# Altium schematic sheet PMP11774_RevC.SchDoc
size 431 x 279 mm; Date: Not shown in title block; ApprovedBy: Not shown in title block; CheckedBy: Not shown in title block; Author: Not shown in title block; CompanyName: Not shown in title block; Engineer: Not shown in title block; Organization: Not shown in title block; Address1: Not shown in title block; Address2: Not shown in title block; Address3: Not shown in title block; Address4: Not shown in title block; DocumentNumber: 1; Revision: Use project parameter SCH_Rev; SheetNumber: 1; SheetTotal: 2; PageSetup: Record=PageOptions¦CenterHorizontal=True¦CenterVertical=True¦PrintScale=0.66¦XCorrection=1.00¦YCorrection=1.00¦PrintKind=0¦BorderSize=5000000¦LeftOffset=0¦BottomOffset=0¦Orientation=2¦PaperLength=4200¦PaperWidth=2970¦Scale=100¦PaperSource=7¦PrintQuality=-3¦MediaType=1¦DitherType=10¦PrintScaleMode=1¦PaperKind=A4¦PaperIndex=9
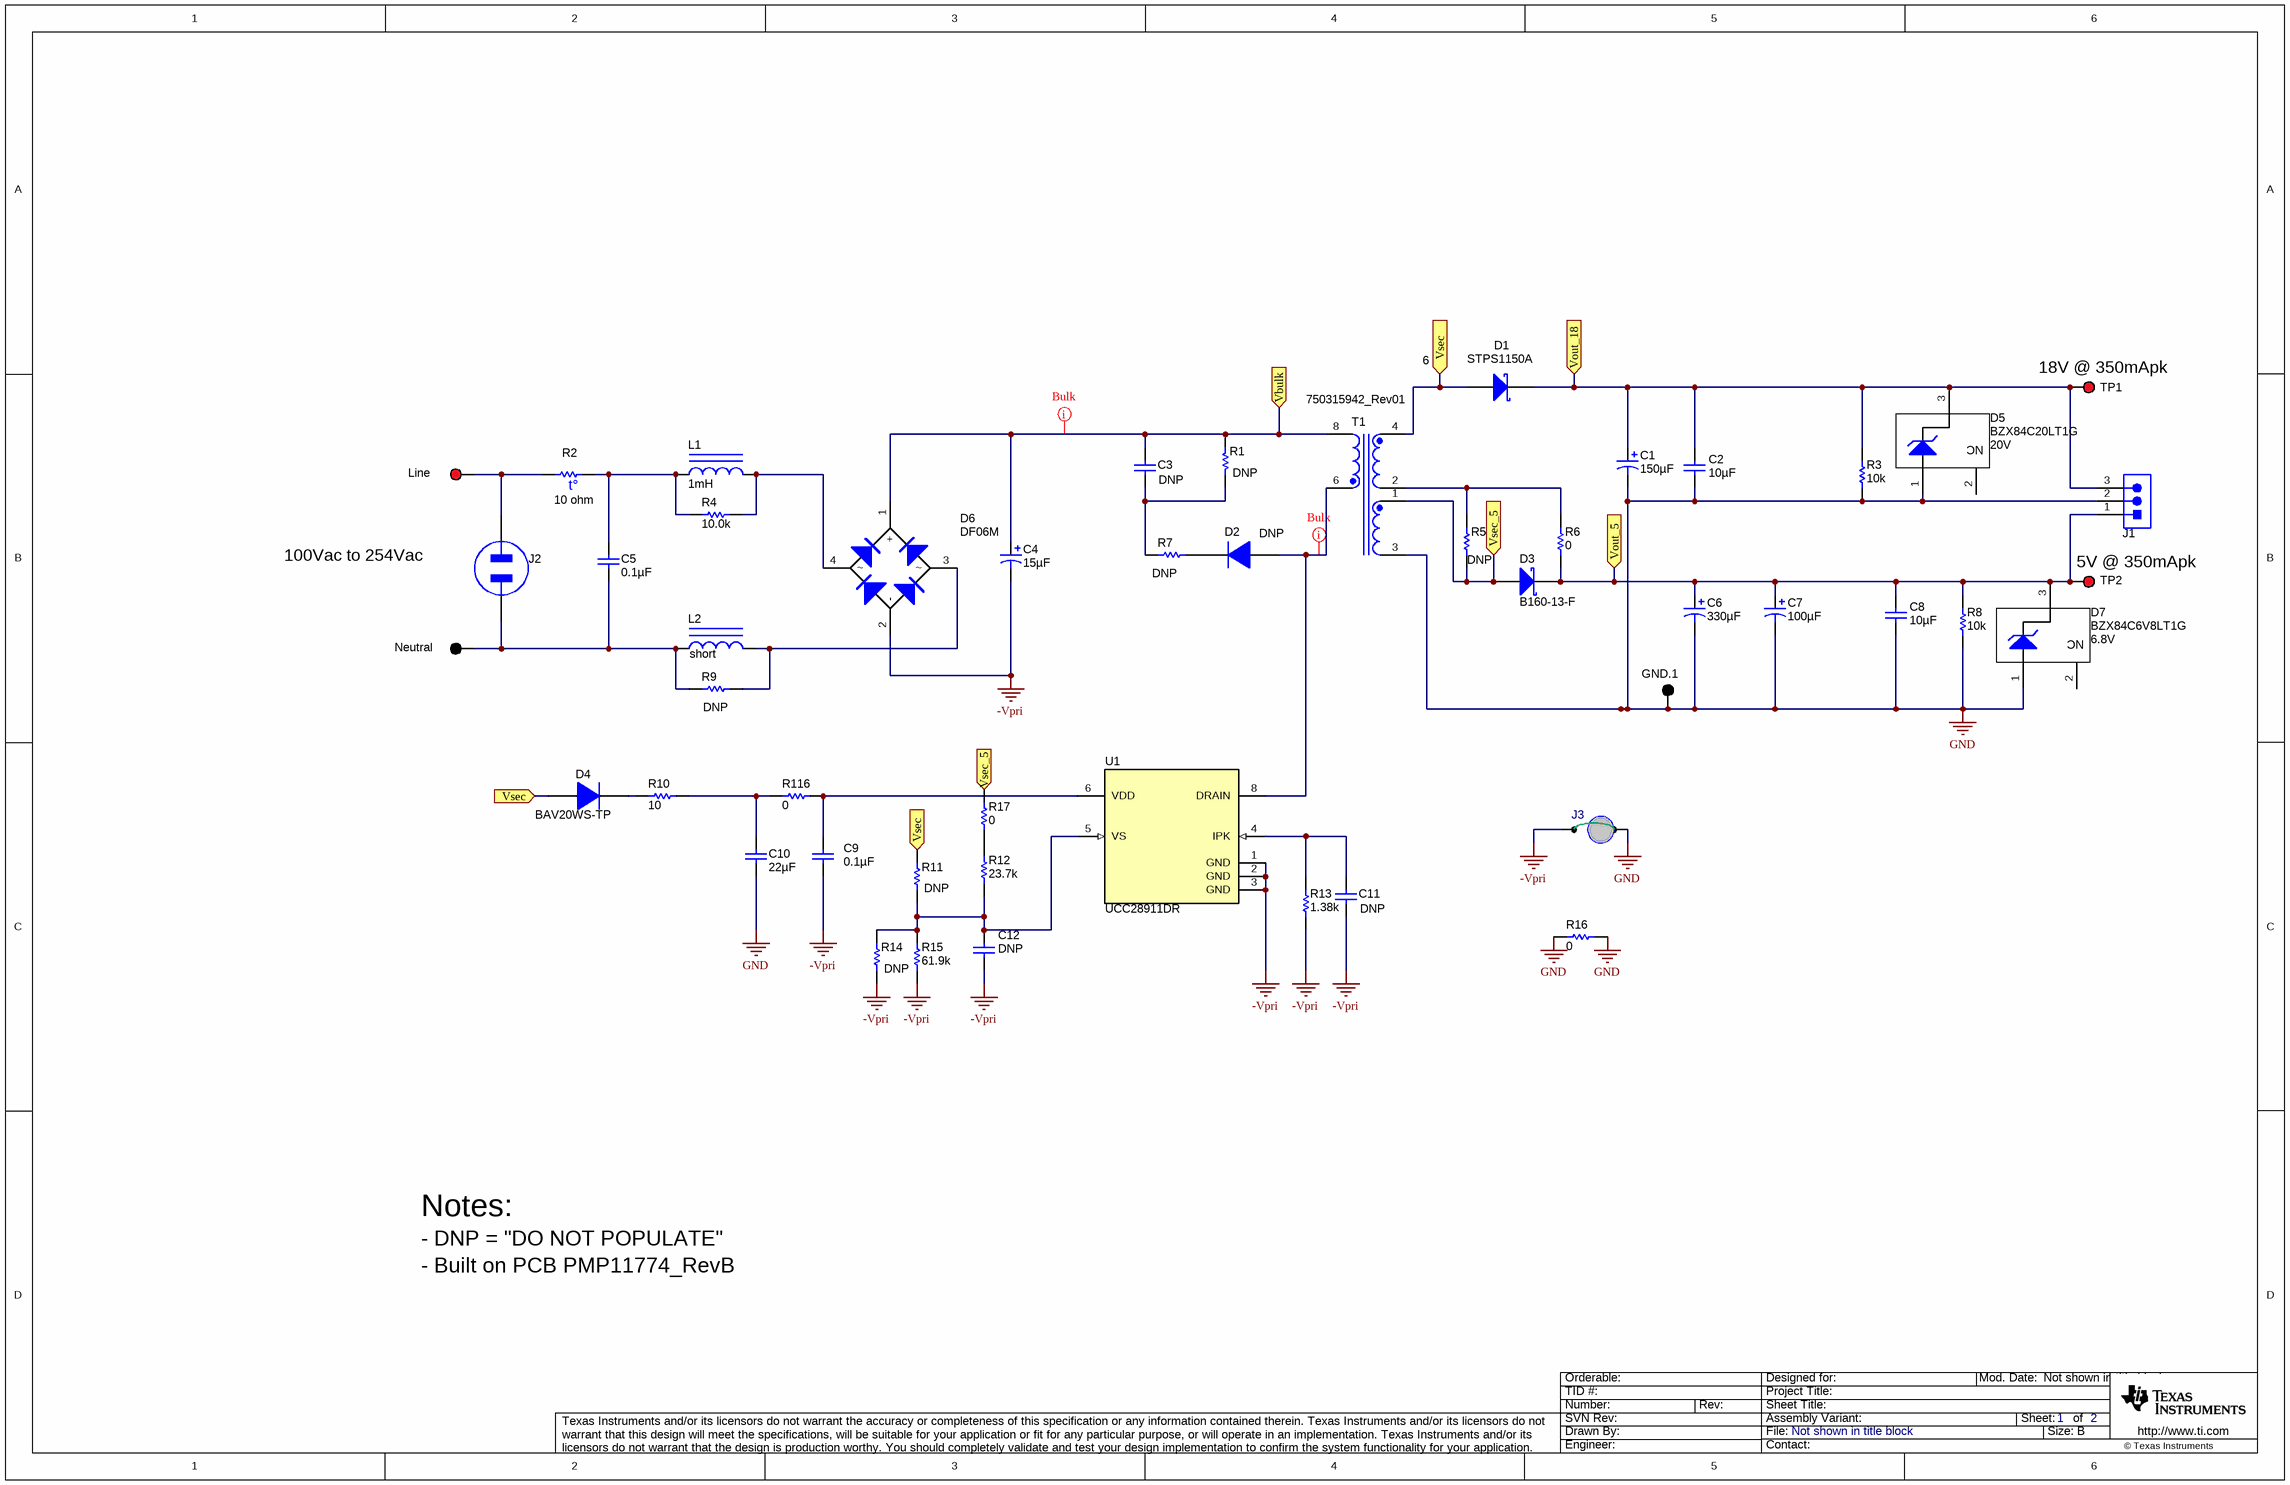
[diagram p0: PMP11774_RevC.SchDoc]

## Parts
C1  ValueDisplayed: 150µF  [FR_630x1120]  (hidden comment: EEU-FR1E151B)
C2  ValueDisplayed: 10µF  [1210]  (hidden comment: GRM32ER71H106KA12L)
C3  value DNP  [0805_HV1]  (hidden comment: QMK212B7102KD-T)
C4  ValueDisplayed: 15µF  [CAPPR5-12.5X20]  (hidden comment: EEUED2G150)
C5  ValueDisplayed: 0.1µF  [R46_1300x1200x600]  (hidden comment: R46KF310050P0K)
C6  ValueDisplayed: 330µF  [ZLH_630x1100]  (hidden comment: 10ZLH330MEFC6.3X11)
C7  ValueDisplayed: 100µF  [FM_630x1120]  (hidden comment: EEU-FM1E101)
C8  ValueDisplayed: 10µF  [1210]  (hidden comment: GRM32ER71H106KA12L)
C9  ValueDisplayed: 0.1µF  [0603]  (hidden comment: 06035C104KAT2A)
C10  ValueDisplayed: 22µF  [1210]  (hidden comment: GRM32ER61E226KE15L)
C11  value DNP  [0603]  (hidden comment: 06035A100JAT2A)
C12  value DNP  [0603]  (hidden comment: 06035A100JAT2A)
D1  STPS1150A  [SMA]
D2  value DNP  [powerDI123]  (hidden comment: DFLR1600-7)
D3  B160-13-F  [SMA]
D4  BAV20WS-TP  [sod-323]
D5  BZX84C20LT1G  value 20V  [SOT-23]
D6  DF06M  [DIOB_DFM]
D7  BZX84C6V8LT1G  value 6.8V  [SOT-23]
GND.1  5001  [Keystone5001]  (value not drawn)
J1  1757255  [TE_1757255]  (value not drawn)
J2  770W-X2/10  [CONN_AC_770W-SERIES]  (value not drawn)
J3  923345-05-C  [923345-05-C]  (value not drawn)
L1  ValueDisplayed: 1mH  [WE-TI_8012]  (hidden comment: 744743102)
L2  value short  [WE-TI_8012]  (hidden comment: 744743102)
Line  5000  [Keystone5000]  (value not drawn)
Neutral  5001  [Keystone5001]  (value not drawn)
R1  value DNP  [1206]  (hidden comment: RC1206FR-07120KL)
R2  value 10 ohm  [THERM_B57236S0]  (hidden comment: B57236S0100M000)
R3  ValueDisplayed: 10k  [0805_HV]  (hidden comment: CRCW080510K0JNEA)
R4  ValueDisplayed: 10.0k  [1206]  (hidden comment: RC1206FR-0710KL)
R5  value DNP  [0805_HV]  (hidden comment: CRCW08050000Z0EA)
R6  ValueDisplayed: 0  [0805_HV]  (hidden comment: CRCW08050000Z0EA)
R7  value DNP  [1206]  (hidden comment: CRCW120610R0JNEA)
R8  ValueDisplayed: 10k  [0805_HV]  (hidden comment: CRCW080510K0JNEA)
R9  value DNP  [1206]  (hidden comment: RC1206FR-0710KL)
R10  ValueDisplayed: 10  [0603]  (hidden comment: CRCW060310R0JNEAHP)
R11  value DNP  [0603]  (hidden comment: CRCW0603110KFKEA)
R12  ValueDisplayed: 23.7k  [0603]  (hidden comment: CRCW060323K7FKEA)
R13  ValueDisplayed: 1.38k  [0603]  (hidden comment: RT0603BRD071K38L)
R14  value DNP  [0603]  (hidden comment: CRCW060391K0JNEA)
R15  ValueDisplayed: 61.9k  [0603]  (hidden comment: RC0603FR-0761K9L)
R16  ValueDisplayed: 0  [RES_TH_CF14]
R17  ValueDisplayed: 0  [1206]  (hidden comment: CRCW12060000Z0EA)
R116  ValueDisplayed: 0  [RES_TH_CF14]
T1  750315942_Rev01  [Wurth_070-5420]
TP1  5000  [Keystone5000]  (value not drawn)
TP2  5000  [Keystone5000]  (value not drawn)
U1  UCC28911DR  [D0007A_N]

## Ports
Vbulk, Vout_5, Vout_18, Vsec, Vsec (in), Vsec_5, Vsec_5 (in)

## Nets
-Vpri: C4.2(-) C9.2 C11.1 C12.1 D6.2(-) J3.1 R13.1 R14.1 R15.1 U1.1(GND) U1.2(GND) U1.3(GND)
GND: C1.2(-) C2.2 C6.2(-) C7.2(-) C8.2 C10.2 D5.1(A) D7.1(A) GND.1.1 J1.2 J3.2 R3.1 R8.1 R16.1 R16.2 T1.3
Vbulk: C3.2 C4.1(+) D6.1(+) R1.1 T1.8 ; port Vbulk
Vout_5: C6.1(+) C7.1(+) C8.1 D3.1(K) D7.3(K) J1.1 R6.1 R8.2 TP2.1 ; port Vout_5
Vout_18: C1.1(+) C2.1 D1.1(K) D5.3(K) J1.3 R3.2 TP1.1 ; port Vout_18
Vsec: D1.2(A) D4.2(A) R11.2 T1.4 ; port Vsec
Vsec_5: D3.2(A) R5.1 R17.2 T1.1 ; port Vsec_5
NetC3_1: C3.1 R1.2 R7.2
NetC5_1: C5.1 L1.1 R2.2 R4.1
NetC5_2: C5.2 J2.1(Neutral) L2.1 Neutral.1 R9.1
NetC9_1: C9.1 R116.2 U1.6(VDD)
NetC10_1: C10.1 R10.2 R116.1
NetC11_2: C11.2 R13.2 U1.4(IPK)
NetC12_2: C12.2 R11.1 R12.1 R14.2 R15.2 U1.5(VS)
NetD2_1: D2.1(K) R7.1
NetD2_2: D2.2(A) T1.6 U1.8(DRAIN)
NetD4_1: D4.1(K) R10.1
NetD6_3: D6.3 L2.2 R9.2
NetD6_4: D6.4 L1.2 R4.2
NetJ2_2: J2.2(Hot) Line.1 R2.1
NetR5_2: R5.2 R6.2 T1.2
NetR12_2: R12.2 R17.1

Not connected (* = marked no-connect by the designer): D5 2(NC); D7 2(NC)

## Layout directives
rule Clearance Constraint [Clearance = 33mil]: Vbulk
rule Clearance Constraint [Clearance = 34mil]: NetD2_2

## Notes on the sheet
- 6
- (near TP1) 18V @ 350mApk
- 100Vac to 254Vac
- (near TP2) 5V @ 350mApk
- Notes:
- - DNP = "DO NOT POPULATE"
- - Built on PCB PMP11774_RevB

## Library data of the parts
C1 = EEU-FR1E151B: CAP, AL, 150 µF, 25 V, +/- 20%,  ohm, TH; Manufacturer: Panasonic; Polarized: Y; CompType: Capacitor; Value: 150uF; U/M: EA; Cap_F: 0.00015; Tolerance_%: 20; Value1: Unknown; VDC_V: 25; Value2: 25V; IRMS_A: 0.455; TaMin_C: -40; TaMax_C: 105; Cap_Case: 6.3x11.2mm
C2 C8 = GRM32ER71H106KA12L: CAP, CERM, 10uF, 50V, +/-10%, X7R, 1210; Manufacturer: MuRata; Polarized: N; CompType: Capacitor; U/M: EA; Cap_F: 0.00001; Tolerance_%: 10; Value1: Unknown; VDC_V: 50; TaMin_C: -55; TaMax_C: 125
C3 = QMK212B7102KD-T: CAP, CERM, 1000 pF, 250 V, +/- 10%, X7R, 0805; Manufacturer: Taiyo Yuden; Polarized: N; CompType: Capacitor; ValueDisplayed: 1000pF; U/M: EA; Cap_F: 0.000000001; Tolerance_%: 10; Value1: Unknown; VDC_V: 250; Value2: 250V; TaMin_C: -55; TaMax_C: 125; Cap_Case: 0805; AEC Category: Q200
C4 = EEUED2G150: CAP, AL, 15 µF, 400 V, +/- 20%, 1.909859 ohm, TH; Manufacturer: Panasonic; Polarized: Y; CompType: Capacitor; Value: 15uF; U/M: EA; Cap_F: 0.000015; Tolerance_%: 20; VDC_V: 400; Value2: 400V; IRMS_A: 0.41; TaMin_C: -25; TaMax_C: 105; AC_Derating: 0.3; AEC Category: Q200
C5 = R46KF310050P0K: CAP, Film, 0.1 µF, 560 V, +/- 10%, TH; Manufacturer: Kemet; Polarized: N; CompType: Capacitor; Value: 0.1uF; U/M: EA; Cap_F: 0.0000001; Tolerance_%: 10; Value1: Unknown; VDC_V: 560; Value2: 560V; TaMin_C: -40; TaMax_C: 110; Cap_Case: 13x12x6; AEC Category: Q200
C6 = 10ZLH330MEFC6.3X11: CAP, AL, 330 µF, 10 V, +/- 20%, 0.094 ohm, TH; Manufacturer: Rubycon; Polarized: Y; CompType: Capacitor; Value: 330uF; U/M: EA; Cap_F: 0.00033; Tolerance_%: 20; VDC_V: 10; Value2: 10V; ESR_ohm: 0.094; IRMS_A: 0.54; TaMin_C: -40; TaMax_C: 105; Cap_Case: 6.3x11mm
C7 = EEU-FM1E101: CAP, AL, 100 µF, 25 V, +/- 20%, 0.13 ohm, TH; Manufacturer: Panasonic; Polarized: Y; CompType: Capacitor; Value: 100uF; U/M: EA; Cap_F: 0.0001; Tolerance_%: 20; VDC_V: 25; Value2: 25V; ESR_ohm: 0.13; IRMS_A: 0.455; TaMin_C: -40; TaMax_C: 105; Cap_Case: 6.3x11.2
C9 = 06035C104KAT2A: CAP, CERM, 0.1uF, 50V, +/-10%, X7R, 0603; Manufacturer: AVX; Polarized: N; CompType: Capacitor; U/M: EA; Cap_F: 0.0000001; Tolerance_%: 10; Value1: Unknown; VDC_V: 50; TaMin_C: -55; TaMax_C: 125
C10 = GRM32ER61E226KE15L: CAP, CERM, 22 µF, 25 V, +/- 10%, X5R, 1210; Manufacturer: MuRata; Polarized: N; CompType: Capacitor; Value: 22uF; U/M: EA; Cap_F: 0.000022; Tolerance_%: 10; ESR_ohm: 0.002; Value1: 0.002 ohm; VDC_V: 25; Value2: 25V; IRMS_A: 3.67; TaMin_C: -55; TaMax_C: 85; AEC Category: Q200
C11 = 06035A100JAT2A: CAP, CERM, 10 pF, 50 V, +/- 5%, C0G/NP0, 0603; Manufacturer: AVX; Polarized: N; CompType: Capacitor; ValueDisplayed: 10pF; U/M: EA; Cap_F: 0.00000000001; Tolerance_%: 5; ESR_ohm: 0.403; Value1: 0.403 ohm; VDC_V: 50; Value2: 50V; TaMin_C: -55; TaMax_C: 125; AEC Category: Q200
C12 = 06035A100JAT2A: CAP, CERM, 10pF, 50V, +/-5%, C0G/NP0, 0603; Manufacturer: AVX; Polarized: N; CompType: Capacitor; U/M: EA; Cap_F: 0.00000000001; Tolerance_%: 5; ESR_Ohm: 0.403; Value1: 0.403 ohm; VDC_V: 50; TaMin_C: -55; TaMax_C: 125
D1 = STPS130A: Diode, Schottky, 150V, 1A, SMA; Manufacturer: ST Microelectronics; U/M: EA; Vf_V: 0.46; Value2: 0.46V; Io_A: 1; TJmax_C: 150
D2 = DFLR1600-7: Diode, Standard Recovery Rectifier, 600 V, 1 A, PowerDI123; Manufacturer: Diodes Inc.; U/M: EA; Vf_V: 1.1; Io_A: 1; Value1: 1A; Vr_V: 600; Value2: 1.1V; TJmax_C: 150; AEC Category: Q101
D3 = B160-13-F: Diode, Schottky, 60 V, 1 A, SMA; Manufacturer: Diodes Inc.; U/M: EA; Vf_V: 0.7; Value: 60V; Value1: 1A; Value2: 0.7V; Io_A: 1; Vr_V: 60; TJmax_C: 150; RJC_CperW: 20; AEC Category: Q101
D4 = BAV20WS-TP: Diode, P-N, 150 V, 0.2 A, SOD-323; Manufacturer: Micro Commercial Components; Value: 150V; U/M: EA; Vf_V: 1.25; Io_A: 0.2; Value1: 0.2A; Vr_V: 150; Value2: 1.25V
D5 = BZX84C20LT1G: Diode, Zener, 20 V, 225 mW, SOT-23; Manufacturer: ON Semiconductor; U/M: EA; Power_W: 0.225; Vz_V: 20; Value1: 0.225W; RJA_CperW: 556; AEC Category: Q101
D6 = DF06M: Diode, Switching-Bridge, 600 V, 1 A, TH; Manufacturer: Diodes Inc.; U/M: EA; Vf_V: 1.1; Value: 600V; Value1: 1A; Value2: 1.1V; Io_A: 1; Vr_V: 600; TJmax_C: 150; AEC Category: Q101
D7 = BZX84C6V8LT1G: Diode, Zener, 6.8 V, 225 mW, SOT-23; Manufacturer: ON Semiconductor; U/M: EA; Power_W: 0.225; Vz_V: 6.8; Value1: 0.225W; RJA_CperW: 556; AEC Category: Q101
GND.1 Neutral = 5001: Test Point, TH, Miniature, Black; Manufacturer: Keystone; CompType: Test Point Loop; U/M: EA
J1 = 1757255: Terminal Block, 5.08mm, 3x1, TH; Manufacturer: TE Connectivity; SymbolCreator: a0799628; CompType: Header; U/M: EA; Note: Mating Part number: 1762208
J2 = 770W-X2/10: AC Receptacle, 2.5A, R/A, TH; Manufacturer: Qualtek Electronics Corporation; SymbolCreator: a0412235; U/M: EA
J3 = 923345-05-C: Jumper Wire, 500mil spacing, Green, pkg of 200; Manufacturer: 3M; SymbolCreator: a0412235; U/M: EA
L1 = 744743102: Inductor, Wirewound, Ferrite, 1 mH, 0.42 A, 2.2 ohm, TH; Manufacturer: Wurth Elektronik; Value: 1mH; Ind_H: 1.0E-3; Imax_A: 0.42; Irms: 0.42A @ 40C rise; Isat: 0.55A @ 10% inductance drop; DCR_ohm: 2.2; Value1: 2.2 ohm; Value2: 0.42A; AEC Category: Q200
L2 = 744743102: Inductor, Wirewound, Ferrite, 1 mH, 0.42 A, 2.2 ohm, TH; Manufacturer: Wurth Elektronik; Ind_H: 1.0E-3; Imax_A: 0.42; Irms: 0.42A @ 40C rise; Isat: 0.55A @ 10% inductance drop; DCR_ohm: 2.2; Value1: 2.2 ohm; Value2: 0.42A; AEC Category: Q200
Line TP1 TP2 = 5000: Test Point, TH, Miniature, Red; Manufacturer: Keystone; CompType: Test Point Loop; U/M: EA
R1 = RC1206FR-07120KL: RES, 120 k, 1%, 0.25 W, 1206; Manufacturer: Yageo America; CompType: Resistor; Res_ohm: 120000; Value_Code: 120k; Tolerance_%: 1; Power_W: 0.25; Value2: 0.25W; VDC_V: 200; TempCo: 100 ppm/C; U/M: EA; AEC Category: Q200
R2 = B57236S0100M000: Thermistor NTC, 10 ohm, 20%, Disc_11.5mmx6mm; Manufacturer: EPCOS Inc; Tolerance_%: 20; Power_W: 2.1; TaMin_C: -55; TaMax_C: 170; U/M: EA
R3 R8 = CRCW080510K0JNEA: RES, 10 k, 5%, 0.125 W, 0805; Manufacturer: Vishay-Dale; CompType: Resistor; Value: 10k; Res_ohm: 10000; Value_Code: 10k0; Tolerance_%: 5; Power_W: 0.125; Value2: 0.125W; VDC_V: 150; TempCo: 200 ppm/C; EIA_Code: E24; U/M: EA; AEC Category: Q200
R4 = RC1206FR-0710KL: RES, 10.0 k, 1%, 0.25 W, 1206; Manufacturer: Yageo America; CompType: Resistor; Value: 10.0k; Res_ohm: 10000; Value_Code: 10k0; Tolerance_%: 1; Power_W: 0.25; Value2: 0.25W; VDC_V: 200; TempCo: 100 ppm/C; EIA_Code: E96; U/M: EA; AEC Category: Q200
R5 = CRCW08050000Z0EA: RES, 0, 5%, 0.125 W, 0805; Manufacturer: Vishay-Dale; CompType: Resistor; Res_ohm: 0; Value_Code: 0000; Tolerance_%: 5; Power_W: 0.125; Value2: 0.125W; VDC_V: 150; TempCo: 200 ppm/C; EIA_Code: E24; U/M: EA; AEC Category: Q200
R6 = CRCW08050000Z0EA: RES, 0, 5%, 0.125 W, 0805; Manufacturer: Vishay-Dale; CompType: Resistor; Value: 0; Value_Code: 0000; Tolerance_%: 5; Power_W: 0.125; Value2: 0.125W; VDC_V: 150; TempCo: 200 ppm/C; EIA_Code: E24; U/M: EA; AEC Category: Q200
R7 = CRCW120610R0JNEA: RES, 10, 5%, 0.25 W, 1206; Manufacturer: Vishay-Dale; CompType: Resistor; Res_ohm: 10; Value_Code: 10R0; Tolerance_%: 5; Power_W: 0.25; Value2: 0.25W; VDC_V: 200; TempCo: 200 ppm/C; EIA_Code: E24; U/M: EA; AEC Category: Q200
R9 = RC1206FR-0710KL: RES, 10.0 k, 1%, 0.25 W, 1206; Manufacturer: Yageo America; CompType: Resistor; ValueDisplayed: 10.0k; Res_ohm: 10000; Value_Code: 10k0; Tolerance_%: 1; Power_W: 0.25; Value2: 0.25W; VDC_V: 200; TempCo: 100 ppm/C; EIA_Code: E96; U/M: EA; AEC Category: Q200
R10 = CRCW060310R0JNEAHP: RES, 10, 5%, 0.25 W, 0603; Manufacturer: Vishay-Dale; CompType: Resistor; Value: 10; Value_Code: 10R0; Tolerance_%: 5; Power_W: 0.25; Value2: 0.25W; VDC_V: 75; TempCo: 200 ppm/C; EIA_Code: E24; U/M: EA
R11 = CRCW0603110KFKEA: RES, 110 k, 1%, 0.1 W, 0603; Manufacturer: Vishay-Dale; CompType: Resistor; Res_ohm: 110000; Value_Code: 110k; Tolerance_%: 1; Power_W: 0.1; Value2: 0.1W; VDC_V: 75; TempCo: 100 ppm/C; EIA_Code: E96; U/M: EA; AEC Category: Q200
R12 = CRCW060323K7FKEA: RES, 23.7 k, 1%, 0.1 W, 0603; Manufacturer: Vishay-Dale; CompType: Resistor; Value: 23.7k; Res_ohm: 23700; Value_Code: 23k7; Tolerance_%: 1; Power_W: 0.1; Value2: 0.1W; VDC_V: 75; TempCo: 100 ppm/C; EIA_Code: E96; U/M: EA; AEC Category: Q200
R13 = RT0603BRD071K38L: RES, 1.38 k, 0.1%, 0.1 W, 0603; Manufacturer: Yageo America; CompType: Resistor; Value: 1.38k; Res_ohm: 1380; Value_Code: 1k38; Tolerance_%: 0.1; Value2: 0.1W; VDC_V: 75; TempCo: 25 ppm/C; EIA_Code: E192; U/M: EA; AEC Category: Q200
R14 = CRCW060391K0JNEA: RES, 91 k, 5%, 0.1 W, 0603; Manufacturer: Vishay-Dale; CompType: Resistor; Res_ohm: 91000; Value_Code: 91k0; Tolerance_%: 5; Power_W: 0.1; Value2: 0.1W; VDC_V: 75; TempCo: 200 ppm/C; EIA_Code: E24; U/M: EA; AEC Category: Q200
R15 = RC0603FR-0761K9L: RES, 61.9 k, 1%, 0.1 W, 0603; Manufacturer: Yageo America; CompType: Resistor; Value: 61.9k; Res_ohm: 61900; Value_Code: 61k9; Tolerance_%: 1; Power_W: 0.1; Value2: 0.1W; VDC_V: 150; TempCo: 200 ppm/C; EIA_Code: E96; U/M: EA; AEC Category: Q200
R16 R116 = CF14JT47R0: RES, 47, 5%, 0.25 W, Axial; Manufacturer: Stackpole Electronics Inc; CompType: Resistor; Value: Jumper Wire; Tolerance_%: 5; Power_W: 0.25; Value2: 0.25W; TempCo: 400 ppm/C; EIA_Code: E24; U/M: EA; AEC Category: Q200
R17 = CRCW12060000Z0EA: RES, 0, 5%, 0.25 W, 1206; Manufacturer: Vishay-Dale; CompType: Resistor; Value: 0; Value_Code: 0000; Tolerance_%: 5; Power_W: 0.25; Value2: 0.25W; VDC_V: 200; TempCo: 200 ppm/C; EIA_Code: E24; U/M: EA; AEC Category: Q200
T1 = 1P2S_EE1685: Transformer, TH; Manufacturer: Texas Instruments; SymbolCreator: Altium
U1 = UCC28911DR: High Voltage Flyback Switcher with Primary-side Regulation and Constant-Current Control, D0007A; Manufacturer: Texas Instruments; SymbolCreator: a0412235; CompType: IC; U/M: EA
